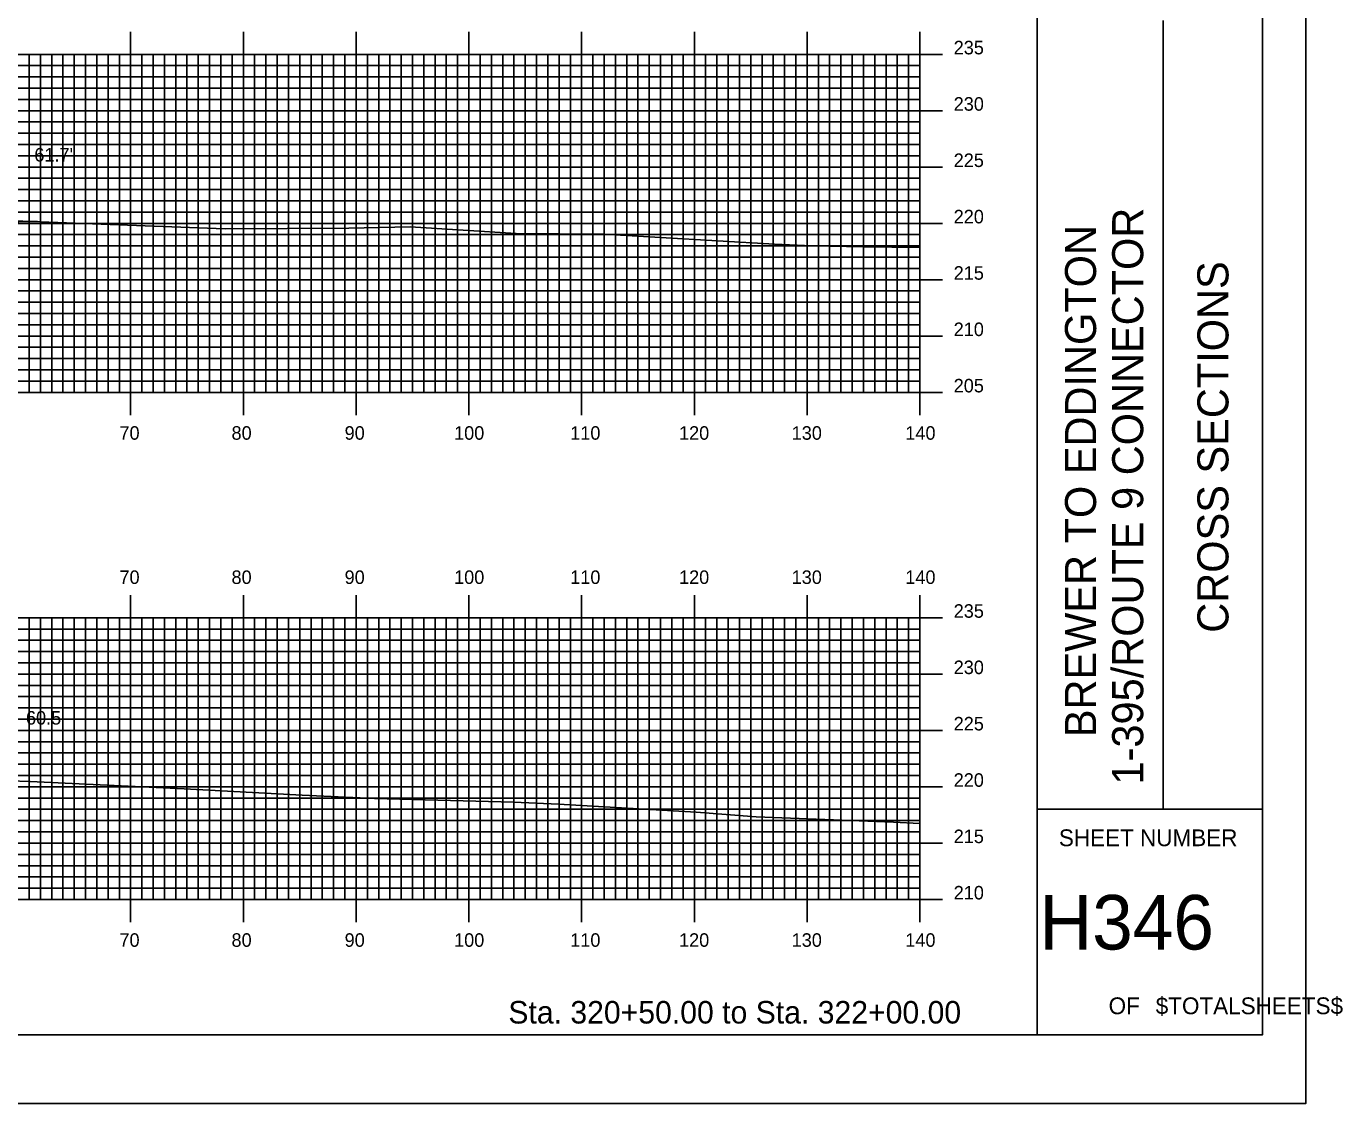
# Model space of a CAD drawing. Extents: x 1820424 to 1820768, y 442591 to 442811.
# Drawn here: x 1820650.9 to 1820767.7, y 442590.5 to 442686.2 of the extents above; entities that cross this region are included whole.
import ezdxf

# ---------------------------------------------------------------- set-up
doc = ezdxf.new("R2010")
doc.units = 0
for name, color, linetype in [('BORDER', 7, 'Continuous'), ('D_Roadway_Centerline', 7, 'Continuous'), ('D_Roadway_SlopeLines', 7, 'Continuous'), ('D_Text_Standard', 7, 'Continuous'), ('H_V ANNOTATION', 7, 'Continuous'), ('MAJOR', 7, 'Continuous'), ('MINOR', 7, 'Continuous'), ('PLOT BOUNDARY', 7, 'Continuous'), ('S_Roadway_Centerline', 7, 'Continuous')]:
    doc.layers.add(name, color=color, linetype=linetype)

msp = doc.modelspace()

# ---------------------------------------------------------------- linework, layer by layer
at = {"layer": 'BORDER'}
for p, q in [((1820740.6, 442596.67), (1820740.6, 442806.67)), ((1820751.79, 442616.67), (1820751.79, 442686.67)), ((1820740.6, 442616.67), (1820760.6, 442616.67))]:
    msp.add_line(p, q, dxfattribs=at)
msp.add_lwpolyline([(1820440.6, 442596.67), (1820760.6, 442596.67), (1820760.6, 442806.67), (1820440.6, 442806.67)], close=True, dxfattribs=at)
at = {"layer": 'D_Roadway_Centerline'}
msp.add_lwpolyline([(1820513.44, 442673.2), (1820514.69, 442673.15), (1820515.94, 442673.02), (1820517.19, 442672.82), (1820518.44, 442672.55), (1820556.03, 442663.15), (1820560.03, 442664.15), (1820570.2, 442666.69), (1820578.2, 442667.01), (1820590.2, 442667.25), (1820602.2, 442667.01), (1820612.2, 442666.61), (1820622.2, 442664.11), (1820626.2, 442663.11), (1820646.94, 442668.3), (1820648.19, 442668.56), (1820649.44, 442668.74), (1820650.69, 442668.83), (1820651.94, 442668.83)], dxfattribs=at)
at = {"layer": 'D_Roadway_SlopeLines'}
msp.add_lwpolyline([(1820626.2, 442663.11), (1820646.94, 442668.3), (1820648.19, 442668.56), (1820649.44, 442668.74), (1820650.69, 442668.83), (1820651.94, 442668.83)], dxfattribs=at)
at = {"layer": 'MAJOR'}
for p, q in [((1820660.2, 442685.67), (1820660.2, 442683.67)), ((1820670.2, 442685.67), (1820670.2, 442683.67)), ((1820680.2, 442685.67), (1820680.2, 442683.67)), ((1820690.2, 442685.67), (1820690.2, 442683.67)), ((1820700.2, 442685.67), (1820700.2, 442683.67)), ((1820710.2, 442685.67), (1820710.2, 442683.67)), ((1820720.2, 442685.67), (1820720.2, 442683.67)), ((1820730.2, 442685.67), (1820730.2, 442683.67)), ((1820450.2, 442683.67), (1820730.2, 442683.67)), ((1820450.2, 442683.67), (1820730.2, 442683.67)), ((1820660.2, 442653.67), (1820660.2, 442683.67)), ((1820670.2, 442653.67), (1820670.2, 442683.67)), ((1820680.2, 442653.67), (1820680.2, 442683.67)), ((1820690.2, 442653.67), (1820690.2, 442683.67)), ((1820700.2, 442653.67), (1820700.2, 442683.67)), ((1820710.2, 442653.67), (1820710.2, 442683.67)), ((1820720.2, 442653.67), (1820720.2, 442683.67)), ((1820732.21, 442683.67), (1820728.2, 442683.67)), ((1820730.2, 442653.67), (1820730.2, 442683.67)), ((1820730.2, 442653.67), (1820730.2, 442683.67)), ((1820450.2, 442678.67), (1820730.2, 442678.67)), ((1820732.21, 442678.67), (1820728.2, 442678.67)), ((1820450.2, 442673.67), (1820730.2, 442673.67)), ((1820732.21, 442673.67), (1820728.2, 442673.67)), ((1820450.2, 442668.67), (1820730.2, 442668.67)), ((1820732.21, 442668.67), (1820728.2, 442668.67)), ((1820450.2, 442663.67), (1820730.2, 442663.67)), ((1820732.21, 442663.67), (1820728.2, 442663.67)), ((1820450.2, 442658.67), (1820730.2, 442658.67)), ((1820732.21, 442658.67), (1820728.2, 442658.67)), ((1820450.2, 442653.67), (1820730.2, 442653.67)), ((1820450.2, 442653.67), (1820730.2, 442653.67)), ((1820660.2, 442651.66), (1820660.2, 442653.67)), ((1820670.2, 442651.66), (1820670.2, 442653.67)), ((1820680.2, 442651.66), (1820680.2, 442653.67)), ((1820690.2, 442651.66), (1820690.2, 442653.67)), ((1820700.2, 442651.66), (1820700.2, 442653.67)), ((1820710.2, 442651.66), (1820710.2, 442653.67)), ((1820720.2, 442651.66), (1820720.2, 442653.67)), ((1820732.21, 442653.67), (1820728.2, 442653.67)), ((1820730.2, 442651.66), (1820730.2, 442653.67)), ((1820660.2, 442635.67), (1820660.2, 442633.67)), ((1820670.2, 442635.67), (1820670.2, 442633.67)), ((1820680.2, 442635.67), (1820680.2, 442633.67)), ((1820690.2, 442635.67), (1820690.2, 442633.67)), ((1820700.2, 442635.67), (1820700.2, 442633.67)), ((1820710.2, 442635.67), (1820710.2, 442633.67)), ((1820720.2, 442635.67), (1820720.2, 442633.67)), ((1820730.2, 442635.67), (1820730.2, 442633.67)), ((1820450.2, 442633.67), (1820730.2, 442633.67)), ((1820450.2, 442633.67), (1820730.2, 442633.67)), ((1820660.2, 442608.67), (1820660.2, 442633.67)), ((1820670.2, 442608.67), (1820670.2, 442633.67)), ((1820680.2, 442608.67), (1820680.2, 442633.67)), ((1820690.2, 442608.67), (1820690.2, 442633.67)), ((1820700.2, 442608.67), (1820700.2, 442633.67)), ((1820710.2, 442608.67), (1820710.2, 442633.67)), ((1820720.2, 442608.67), (1820720.2, 442633.67)), ((1820732.21, 442633.67), (1820728.2, 442633.67)), ((1820730.2, 442608.67), (1820730.2, 442633.67)), ((1820730.2, 442608.67), (1820730.2, 442633.67)), ((1820450.2, 442628.67), (1820730.2, 442628.67)), ((1820732.21, 442628.67), (1820728.2, 442628.67)), ((1820450.2, 442623.67), (1820730.2, 442623.67)), ((1820732.21, 442623.67), (1820728.2, 442623.67)), ((1820450.2, 442618.67), (1820730.2, 442618.67)), ((1820732.21, 442618.67), (1820728.2, 442618.67)), ((1820450.2, 442613.67), (1820730.2, 442613.67)), ((1820732.21, 442613.67), (1820728.2, 442613.67)), ((1820450.2, 442608.67), (1820730.2, 442608.67)), ((1820450.2, 442608.67), (1820730.2, 442608.67)), ((1820660.2, 442606.66), (1820660.2, 442608.67)), ((1820670.2, 442606.66), (1820670.2, 442608.67)), ((1820680.2, 442606.66), (1820680.2, 442608.67)), ((1820690.2, 442606.66), (1820690.2, 442608.67)), ((1820700.2, 442606.66), (1820700.2, 442608.67)), ((1820710.2, 442606.66), (1820710.2, 442608.67)), ((1820720.2, 442606.66), (1820720.2, 442608.67)), ((1820732.21, 442608.67), (1820728.2, 442608.67)), ((1820730.2, 442606.66), (1820730.2, 442608.67))]:
    msp.add_line(p, q, dxfattribs=at)
at = {"layer": 'MINOR'}
for p, q in [((1820651.2, 442653.67), (1820651.2, 442683.67)), ((1820652.2, 442653.67), (1820652.2, 442683.67)), ((1820653.2, 442653.67), (1820653.2, 442683.67)), ((1820654.2, 442653.67), (1820654.2, 442683.67)), ((1820655.2, 442653.67), (1820655.2, 442683.67)), ((1820656.2, 442653.67), (1820656.2, 442683.67)), ((1820657.2, 442653.67), (1820657.2, 442683.67)), ((1820658.2, 442653.67), (1820658.2, 442683.67)), ((1820659.2, 442653.67), (1820659.2, 442683.67)), ((1820661.2, 442653.67), (1820661.2, 442683.67)), ((1820662.2, 442653.67), (1820662.2, 442683.67)), ((1820663.2, 442653.67), (1820663.2, 442683.67)), ((1820664.2, 442653.67), (1820664.2, 442683.67)), ((1820665.2, 442653.67), (1820665.2, 442683.67)), ((1820666.2, 442653.67), (1820666.2, 442683.67)), ((1820667.2, 442653.67), (1820667.2, 442683.67)), ((1820668.2, 442653.67), (1820668.2, 442683.67)), ((1820669.2, 442653.67), (1820669.2, 442683.67)), ((1820671.2, 442653.67), (1820671.2, 442683.67)), ((1820672.2, 442653.67), (1820672.2, 442683.67)), ((1820673.2, 442653.67), (1820673.2, 442683.67)), ((1820674.2, 442653.67), (1820674.2, 442683.67)), ((1820675.2, 442653.67), (1820675.2, 442683.67)), ((1820676.2, 442653.67), (1820676.2, 442683.67)), ((1820677.2, 442653.67), (1820677.2, 442683.67)), ((1820678.2, 442653.67), (1820678.2, 442683.67)), ((1820679.2, 442653.67), (1820679.2, 442683.67)), ((1820681.2, 442653.67), (1820681.2, 442683.67)), ((1820682.2, 442653.67), (1820682.2, 442683.67)), ((1820683.2, 442653.67), (1820683.2, 442683.67)), ((1820684.2, 442653.67), (1820684.2, 442683.67)), ((1820685.2, 442653.67), (1820685.2, 442683.67)), ((1820686.2, 442653.67), (1820686.2, 442683.67)), ((1820687.2, 442653.67), (1820687.2, 442683.67)), ((1820688.2, 442653.67), (1820688.2, 442683.67)), ((1820689.2, 442653.67), (1820689.2, 442683.67)), ((1820691.2, 442653.67), (1820691.2, 442683.67)), ((1820692.2, 442653.67), (1820692.2, 442683.67)), ((1820693.2, 442653.67), (1820693.2, 442683.67)), ((1820694.2, 442653.67), (1820694.2, 442683.67)), ((1820695.2, 442653.67), (1820695.2, 442683.67)), ((1820696.2, 442653.67), (1820696.2, 442683.67)), ((1820697.2, 442653.67), (1820697.2, 442683.67)), ((1820698.2, 442653.67), (1820698.2, 442683.67)), ((1820699.2, 442653.67), (1820699.2, 442683.67)), ((1820701.2, 442653.67), (1820701.2, 442683.67)), ((1820702.2, 442653.67), (1820702.2, 442683.67)), ((1820703.2, 442653.67), (1820703.2, 442683.67)), ((1820704.2, 442653.67), (1820704.2, 442683.67)), ((1820705.2, 442653.67), (1820705.2, 442683.67)), ((1820706.2, 442653.67), (1820706.2, 442683.67)), ((1820707.2, 442653.67), (1820707.2, 442683.67)), ((1820708.2, 442653.67), (1820708.2, 442683.67)), ((1820709.2, 442653.67), (1820709.2, 442683.67)), ((1820711.2, 442653.67), (1820711.2, 442683.67)), ((1820712.2, 442653.67), (1820712.2, 442683.67)), ((1820713.2, 442653.67), (1820713.2, 442683.67)), ((1820714.2, 442653.67), (1820714.2, 442683.67)), ((1820715.2, 442653.67), (1820715.2, 442683.67)), ((1820716.2, 442653.67), (1820716.2, 442683.67)), ((1820717.2, 442653.67), (1820717.2, 442683.67)), ((1820718.2, 442653.67), (1820718.2, 442683.67)), ((1820719.2, 442653.67), (1820719.2, 442683.67)), ((1820721.2, 442653.67), (1820721.2, 442683.67)), ((1820722.2, 442653.67), (1820722.2, 442683.67)), ((1820723.2, 442653.67), (1820723.2, 442683.67)), ((1820724.2, 442653.67), (1820724.2, 442683.67)), ((1820725.2, 442653.67), (1820725.2, 442683.67)), ((1820726.2, 442653.67), (1820726.2, 442683.67)), ((1820727.2, 442653.67), (1820727.2, 442683.67)), ((1820728.2, 442653.67), (1820728.2, 442683.67)), ((1820729.2, 442653.67), (1820729.2, 442683.67)), ((1820450.2, 442682.67), (1820730.2, 442682.67)), ((1820730.2, 442682.67), (1820728.2, 442682.67)), ((1820450.2, 442681.67), (1820730.2, 442681.67)), ((1820450.2, 442680.67), (1820730.2, 442680.67)), ((1820730.2, 442681.67), (1820728.2, 442681.67)), ((1820730.2, 442680.67), (1820728.2, 442680.67)), ((1820450.2, 442679.67), (1820730.2, 442679.67)), ((1820730.2, 442679.67), (1820728.2, 442679.67)), ((1820450.2, 442677.67), (1820730.2, 442677.67)), ((1820730.2, 442677.67), (1820728.2, 442677.67)), ((1820450.2, 442676.67), (1820730.2, 442676.67)), ((1820730.2, 442676.67), (1820728.2, 442676.67)), ((1820450.2, 442675.67), (1820730.2, 442675.67)), ((1820730.2, 442675.67), (1820728.2, 442675.67)), ((1820450.2, 442674.67), (1820730.2, 442674.67)), ((1820730.2, 442674.67), (1820728.2, 442674.67)), ((1820450.2, 442672.67), (1820730.2, 442672.67)), ((1820730.2, 442672.67), (1820728.2, 442672.67)), ((1820450.2, 442671.67), (1820730.2, 442671.67)), ((1820730.2, 442671.67), (1820728.2, 442671.67)), ((1820450.2, 442670.67), (1820730.2, 442670.67)), ((1820730.2, 442670.67), (1820728.2, 442670.67)), ((1820450.2, 442669.67), (1820730.2, 442669.67)), ((1820730.2, 442669.67), (1820728.2, 442669.67)), ((1820450.2, 442667.67), (1820730.2, 442667.67)), ((1820450.2, 442666.67), (1820730.2, 442666.67)), ((1820730.2, 442667.67), (1820728.2, 442667.67)), ((1820730.2, 442666.67), (1820728.2, 442666.67)), ((1820450.2, 442665.67), (1820730.2, 442665.67)), ((1820730.2, 442665.67), (1820728.2, 442665.67)), ((1820450.2, 442664.67), (1820730.2, 442664.67)), ((1820730.2, 442664.67), (1820728.2, 442664.67)), ((1820450.2, 442662.67), (1820730.2, 442662.67)), ((1820730.2, 442662.67), (1820728.2, 442662.67)), ((1820450.2, 442661.67), (1820730.2, 442661.67)), ((1820730.2, 442661.67), (1820728.2, 442661.67)), ((1820450.2, 442660.67), (1820730.2, 442660.67)), ((1820450.2, 442659.67), (1820730.2, 442659.67)), ((1820730.2, 442660.67), (1820728.2, 442660.67)), ((1820730.2, 442659.67), (1820728.2, 442659.67)), ((1820450.2, 442657.67), (1820730.2, 442657.67)), ((1820730.2, 442657.67), (1820728.2, 442657.67)), ((1820450.2, 442656.67), (1820730.2, 442656.67)), ((1820730.2, 442656.67), (1820728.2, 442656.67)), ((1820450.2, 442655.67), (1820730.2, 442655.67)), ((1820730.2, 442655.67), (1820728.2, 442655.67)), ((1820450.2, 442654.67), (1820730.2, 442654.67)), ((1820730.2, 442654.67), (1820728.2, 442654.67)), ((1820450.2, 442632.67), (1820730.2, 442632.67)), ((1820651.2, 442608.67), (1820651.2, 442633.67)), ((1820652.2, 442608.67), (1820652.2, 442633.67)), ((1820653.2, 442608.67), (1820653.2, 442633.67)), ((1820654.2, 442608.67), (1820654.2, 442633.67)), ((1820655.2, 442608.67), (1820655.2, 442633.67)), ((1820656.2, 442608.67), (1820656.2, 442633.67)), ((1820657.2, 442608.67), (1820657.2, 442633.67)), ((1820658.2, 442608.67), (1820658.2, 442633.67)), ((1820659.2, 442608.67), (1820659.2, 442633.67)), ((1820661.2, 442608.67), (1820661.2, 442633.67)), ((1820662.2, 442608.67), (1820662.2, 442633.67)), ((1820663.2, 442608.67), (1820663.2, 442633.67)), ((1820664.2, 442608.67), (1820664.2, 442633.67)), ((1820665.2, 442608.67), (1820665.2, 442633.67)), ((1820666.2, 442608.67), (1820666.2, 442633.67)), ((1820667.2, 442608.67), (1820667.2, 442633.67)), ((1820668.2, 442608.67), (1820668.2, 442633.67)), ((1820669.2, 442608.67), (1820669.2, 442633.67)), ((1820671.2, 442608.67), (1820671.2, 442633.67)), ((1820672.2, 442608.67), (1820672.2, 442633.67)), ((1820673.2, 442608.67), (1820673.2, 442633.67)), ((1820674.2, 442608.67), (1820674.2, 442633.67)), ((1820675.2, 442608.67), (1820675.2, 442633.67)), ((1820676.2, 442608.67), (1820676.2, 442633.67)), ((1820677.2, 442608.67), (1820677.2, 442633.67)), ((1820678.2, 442608.67), (1820678.2, 442633.67)), ((1820679.2, 442608.67), (1820679.2, 442633.67)), ((1820681.2, 442608.67), (1820681.2, 442633.67)), ((1820682.2, 442608.67), (1820682.2, 442633.67)), ((1820683.2, 442608.67), (1820683.2, 442633.67)), ((1820684.2, 442608.67), (1820684.2, 442633.67)), ((1820685.2, 442608.67), (1820685.2, 442633.67)), ((1820686.2, 442608.67), (1820686.2, 442633.67)), ((1820687.2, 442608.67), (1820687.2, 442633.67)), ((1820688.2, 442608.67), (1820688.2, 442633.67)), ((1820689.2, 442608.67), (1820689.2, 442633.67)), ((1820691.2, 442608.67), (1820691.2, 442633.67)), ((1820692.2, 442608.67), (1820692.2, 442633.67)), ((1820693.2, 442608.67), (1820693.2, 442633.67)), ((1820694.2, 442608.67), (1820694.2, 442633.67)), ((1820695.2, 442608.67), (1820695.2, 442633.67)), ((1820696.2, 442608.67), (1820696.2, 442633.67)), ((1820697.2, 442608.67), (1820697.2, 442633.67)), ((1820698.2, 442608.67), (1820698.2, 442633.67)), ((1820699.2, 442608.67), (1820699.2, 442633.67)), ((1820701.2, 442608.67), (1820701.2, 442633.67)), ((1820702.2, 442608.67), (1820702.2, 442633.67)), ((1820703.2, 442608.67), (1820703.2, 442633.67)), ((1820704.2, 442608.67), (1820704.2, 442633.67)), ((1820705.2, 442608.67), (1820705.2, 442633.67)), ((1820706.2, 442608.67), (1820706.2, 442633.67)), ((1820707.2, 442608.67), (1820707.2, 442633.67)), ((1820708.2, 442608.67), (1820708.2, 442633.67)), ((1820709.2, 442608.67), (1820709.2, 442633.67)), ((1820711.2, 442608.67), (1820711.2, 442633.67)), ((1820712.2, 442608.67), (1820712.2, 442633.67)), ((1820713.2, 442608.67), (1820713.2, 442633.67)), ((1820714.2, 442608.67), (1820714.2, 442633.67)), ((1820715.2, 442608.67), (1820715.2, 442633.67)), ((1820716.2, 442608.67), (1820716.2, 442633.67)), ((1820717.2, 442608.67), (1820717.2, 442633.67)), ((1820718.2, 442608.67), (1820718.2, 442633.67)), ((1820719.2, 442608.67), (1820719.2, 442633.67)), ((1820721.2, 442608.67), (1820721.2, 442633.67)), ((1820722.2, 442608.67), (1820722.2, 442633.67)), ((1820723.2, 442608.67), (1820723.2, 442633.67)), ((1820724.2, 442608.67), (1820724.2, 442633.67)), ((1820725.2, 442608.67), (1820725.2, 442633.67)), ((1820726.2, 442608.67), (1820726.2, 442633.67)), ((1820727.2, 442608.67), (1820727.2, 442633.67)), ((1820728.2, 442608.67), (1820728.2, 442633.67)), ((1820730.2, 442632.67), (1820728.2, 442632.67)), ((1820729.2, 442608.67), (1820729.2, 442633.67)), ((1820450.2, 442631.67), (1820730.2, 442631.67)), ((1820730.2, 442631.67), (1820728.2, 442631.67)), ((1820450.2, 442630.67), (1820730.2, 442630.67)), ((1820730.2, 442630.67), (1820728.2, 442630.67)), ((1820450.2, 442629.67), (1820730.2, 442629.67)), ((1820730.2, 442629.67), (1820728.2, 442629.67)), ((1820450.2, 442627.67), (1820730.2, 442627.67)), ((1820730.2, 442627.67), (1820728.2, 442627.67)), ((1820450.2, 442626.67), (1820730.2, 442626.67)), ((1820450.2, 442625.67), (1820730.2, 442625.67)), ((1820730.2, 442626.67), (1820728.2, 442626.67)), ((1820730.2, 442625.67), (1820728.2, 442625.67)), ((1820450.2, 442624.67), (1820730.2, 442624.67)), ((1820730.2, 442624.67), (1820728.2, 442624.67)), ((1820450.2, 442622.67), (1820730.2, 442622.67)), ((1820730.2, 442622.67), (1820728.2, 442622.67)), ((1820450.2, 442621.67), (1820730.2, 442621.67)), ((1820730.2, 442621.67), (1820728.2, 442621.67)), ((1820450.2, 442620.67), (1820730.2, 442620.67)), ((1820730.2, 442620.67), (1820728.2, 442620.67)), ((1820450.2, 442619.67), (1820730.2, 442619.67)), ((1820730.2, 442619.67), (1820728.2, 442619.67)), ((1820450.2, 442617.67), (1820730.2, 442617.67)), ((1820730.2, 442617.67), (1820728.2, 442617.67)), ((1820450.2, 442616.67), (1820730.2, 442616.67)), ((1820730.2, 442616.67), (1820728.2, 442616.67)), ((1820450.2, 442615.67), (1820730.2, 442615.67)), ((1820730.2, 442615.67), (1820728.2, 442615.67)), ((1820450.2, 442614.67), (1820730.2, 442614.67)), ((1820730.2, 442614.67), (1820728.2, 442614.67)), ((1820450.2, 442612.67), (1820730.2, 442612.67)), ((1820450.2, 442611.67), (1820730.2, 442611.67)), ((1820730.2, 442612.67), (1820728.2, 442612.67)), ((1820730.2, 442611.67), (1820728.2, 442611.67)), ((1820450.2, 442610.67), (1820730.2, 442610.67)), ((1820730.2, 442610.67), (1820728.2, 442610.67)), ((1820450.2, 442609.67), (1820730.2, 442609.67)), ((1820730.2, 442609.67), (1820728.2, 442609.67))]:
    msp.add_line(p, q, dxfattribs=at)
at = {"layer": 'PLOT BOUNDARY'}
msp.add_lwpolyline([(1820424.42, 442590.55), (1820764.42, 442590.55), (1820764.42, 442810.55), (1820424.42, 442810.55)], close=True, dxfattribs=at)
at = {"layer": 'S_Roadway_Centerline'}
for points in [[(1820647.6, 442668.99), (1820651.41, 442668.85), (1820659.91, 442668.51), (1820668.6, 442668.19), (1820679.54, 442668.25), (1820685, 442668.35), (1820694.4, 442667.77), (1820702.13, 442667.7), (1820717.3, 442666.83), (1820720.65, 442666.67), (1820725.23, 442666.58), (1820730.2, 442666.52)], [(1820647.54, 442619.26), (1820651.3, 442619.14), (1820664.96, 442618.48), (1820675.42, 442617.92), (1820681.82, 442617.62), (1820694.18, 442617.3), (1820698.15, 442617.13), (1820710.36, 442616.42), (1820715.69, 442616.01), (1820727.86, 442615.54), (1820730.2, 442615.42)]]:
    msp.add_lwpolyline(points, dxfattribs=at)

# ---------------------------------------------------------------- texts
at = {"layer": 'BORDER'}
for s, p in [('1-395/ROUTE 9 CONNECTOR', (1820750.01, 442618.87)), ('BREWER TO EDDINGTON', (1820745.83, 442623.07)), ('CROSS SECTIONS', (1820757.57, 442632.34))]:
    msp.add_text(s, height=2.7557, rotation=90, dxfattribs=at).set_placement(p)
for s, height, p in [('SHEET NUMBER', 1.4905, (1820742.53, 442613.4)), ('H346', 4.839, (1820740.81, 442604.23)), ('OF', 1.491, (1820746.94, 442598.49)), ('$TOTALSHEETS$', 1.4905, (1820751.12, 442598.49))]:
    msp.add_text(s, height=height, dxfattribs=at).set_placement(p)
at = {"layer": 'D_Text_Standard'}
for s, p in [("61.7'", (1820651.66, 442674.16)), ("60.5'", (1820650.92, 442624.19))]:
    msp.add_text(s, height=1.2, dxfattribs=at).set_placement(p)
at = {"layer": 'H_V ANNOTATION'}
for s, height, p in [('235', 1.2, (1820733.2, 442683.67)), ('230', 1.2, (1820733.2, 442678.67)), ('225', 1.2, (1820733.2, 442673.67)), ('220', 1.2, (1820733.2, 442668.67)), ('215', 1.2, (1820733.2, 442663.67)), ('210', 1.2, (1820733.2, 442658.67)), ('205', 1.2, (1820733.2, 442653.67)), ('70', 1.2, (1820659.21, 442649.47)), ('80', 1.2, (1820669.15, 442649.47)), ('90', 1.2, (1820679.18, 442649.47)), ('100', 1.2, (1820688.89, 442649.47)), ('110', 1.2, (1820699.19, 442649.47)), ('120', 1.2, (1820708.84, 442649.47)), ('130', 1.2, (1820718.83, 442649.47)), ('140', 1.2, (1820728.91, 442649.47)), ('70', 1.2, (1820659.21, 442636.67)), ('80', 1.2, (1820669.15, 442636.67)), ('90', 1.2, (1820679.18, 442636.67)), ('100', 1.2, (1820688.89, 442636.67)), ('110', 1.2, (1820699.19, 442636.67)), ('120', 1.2, (1820708.84, 442636.67)), ('130', 1.2, (1820718.83, 442636.67)), ('140', 1.2, (1820728.91, 442636.67)), ('235', 1.2, (1820733.2, 442633.67)), ('230', 1.2, (1820733.2, 442628.67)), ('225', 1.2, (1820733.2, 442623.67)), ('220', 1.2, (1820733.2, 442618.67)), ('215', 1.2, (1820733.2, 442613.67)), ('210', 1.2, (1820733.2, 442608.67)), ('70', 1.2, (1820659.21, 442604.47)), ('80', 1.2, (1820669.15, 442604.47)), ('90', 1.2, (1820679.18, 442604.47)), ('100', 1.2, (1820688.89, 442604.47)), ('110', 1.2, (1820699.19, 442604.47)), ('120', 1.2, (1820708.84, 442604.47)), ('130', 1.2, (1820718.83, 442604.47)), ('140', 1.2, (1820728.91, 442604.47)), ('Sta. 320+50.00 to Sta. 322+00.00', 2.0004, (1820693.7, 442597.66))]:
    msp.add_text(s, height=height, dxfattribs=at).set_placement(p)

doc.saveas('drawing.dxf')
